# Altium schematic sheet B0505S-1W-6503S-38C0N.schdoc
size 277 x 190 mm; Device: default297x210; Symbol: default297x210; Name: default297x210; Date: 2025.07.04; Rev: V1.1; Size: "A4"; Id: /; File: B0505S-1W-6503S-38C0N; Sheet: /; @Page No: 1; @Page Count: 1; @Schematic Name: B0505S-1W-6503S-38C0N; @Project Name: 全桥隔离电源-B0505S-1W-6503S-38C0N; @Board Name: B0505S-1W-6503S-38C0N; @Update Date: 2025-07-04; @Create Time: 13:55:23; @Update Time: 16:14:59; @Page Name: B0505S-1W-6503S-38C0N; @Create Date: 2025-06-24
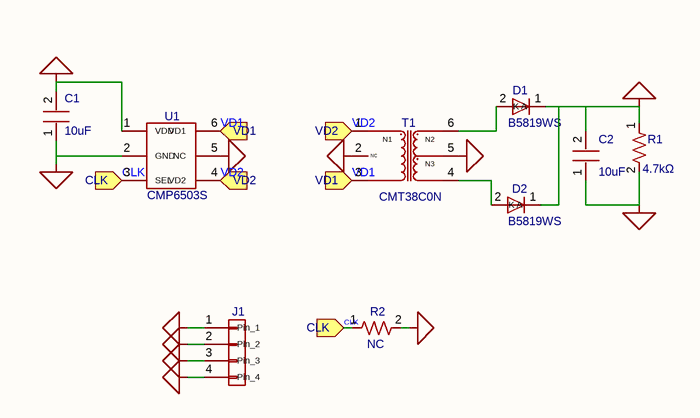
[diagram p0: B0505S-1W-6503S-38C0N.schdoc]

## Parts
C1  10uF  [C0603]
C2  10uF  [C0603]
D1  B5819WS  [SOD-323_L1.8-W1.3-LS2.5-RD]
D2  B5819WS  [SOD-323_L1.8-W1.3-LS2.5-RD]
J1  Connector_Generic_Conn_01x04  [coileasy:PinHeader_01x04_P2.54mm_Vertical]  (value not drawn)
R1  4.7kΩ  [R0603]
R2  NC  [R0603]
T1  CMT38C0N  [coileasy:CMT38xxx]
U1  CMP6503S  [coileasy:SOT-23-6]

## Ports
CLK (in), VD1 (in), VD2 (in)

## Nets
0V: C2.1 J1.3(Pin_3) R1.2 T1.5
+VO: C2.2 D1.1(K) D2.1(K) J1.4(Pin_4) R1.1
GND: C1.1 J1.1(Pin_1) R2.2 U1.2(GND)
VIN: C1.2 J1.2(Pin_2) T1.2 U1.1(VDD) U1.5(NC)
CLK: R2.1 U1.3(SEL) ; port CLK
VD1: T1.3 U1.6(VD1) ; port VD1
VD2: T1.1 U1.4(VD2) ; port VD2
NetD1_2: D1.2(A) T1.6
NetD2_2: D2.2(A) T1.4

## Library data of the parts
C1 C2 = 0603X106K100NT: 容值:10uF;精度:±10%;额定电压:10V;材质(温度系数):X5R;; Manufacturer: FH(风华); Symbol: My_Library_C; AddInBom: yes; ModelId: ac125912035d415993ca9572d50418b1; ModelName: C0603_L1.6-W0.8-H0.8; ModelTransform: 62.992,31.496,0,0,0,0,0,0,0; Tolerance: ±10%; Voltage Rated: 10V; Temperature Coefficient: X5R
D1 D2 = B5819WS_C64886: 二极管配置:独立式;正向压降(Vf):900mV@3A;直流反向耐压(Vr):40V;整流电流:1A;; Manufacturer: MDD(辰达半导体); Symbol: My_Library_D; AddInBom: yes; ModelId: 7459fe65e23146c0a8d836e46a0add72; ModelTransform: 104.3305,51.181,0,0,0,0,0,0,0; Diode Configuration: 独立式; Reverse Voltage (Vr): 40V; Rectified Current: 1A; Reverse Leakage Current (Ir): 1mA@40V
J1 = Connector_Generic_Conn_01x04: Generic connector, single row, 01x04, script generated (kicad-library-utils/schlib/autogen/connector/); Users: REF**; ki_fp_filters: Connector*:*_1x??_*; AddInBom: yes
R1 = RC0603FR-074K7L: 电阻类型:厚膜电阻;阻值:4.7kΩ;精度:±1%;功率:100mW;最大工作电压:75V;温度系数:±100ppm/℃;; Manufacturer: YAGEO(国巨); Symbol: R; AddInBom: yes; ModelId: fc143cca1e79419f9cd78b61e9279f08; ModelTransform: 31.8897,63.7794,0,90,0,0,0,0,0; Tolerance: ±1%; Power(Watts): 100mW; Overload Voltage (Max): 75V
R2 = R: 电阻类型:厚膜电阻;阻值:10kΩ;精度:±1%;功率:100mW;最大工作电压:75V;温度系数:±100ppm/℃;; AddInBom: yes; Tolerance: ±1%; Power(Watts): 100mW; Overload Voltage (Max): 75V
T1 = MYLibrary _CMT38xxxx: Users: REF**; AddInBom: yes
U1 = CMP6503S: CMP6503S 是低噪声、低 EMI 辐射的全桥式隔离电源变压器驱动器，特别适合于小型化的隔离电源方案，属于 线 易 ChipMate(CM) 系 列 的 电 源 解 决 方 案 。CMP6503S 内 部 集 成 两 对 N 型 和 P 型 功 率MOSFET，通过芯片内部集成振荡器提供具有精准时序和死区时间的互补驱动信号。驱动器芯片 CMP6503S和变压器配合必要的容阻和整流二极管，可以实现5.0V 输入/5.0V 输出的 200 mA 隔离非稳压电源；或者 3.3V 输入/3.3V 输出的 10; Manufacturer: coileasy(线易); Symbol: MYLibrary_CMP6xxxx; AddInBom: yes; ModelId: 7ba65df16e7b4570af156e925f9c37fe; ModelName: SOT-23-5_L2.9-W1.6-P0.95-LS2.8-BR; ModelTransform: 114.173,114.173,0,90,0,0,0,0,0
